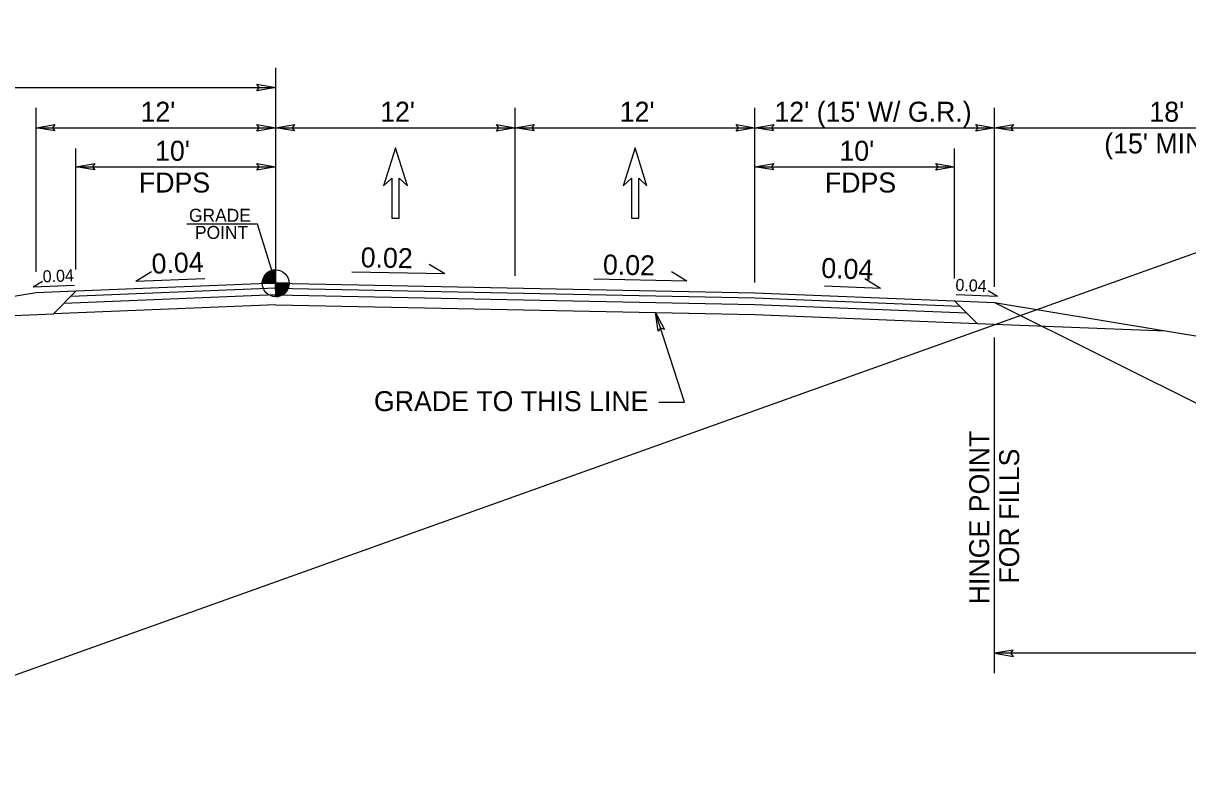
# Model space of a CAD drawing. Extents: x 1553195 to 1553792, y 810516 to 810787.
# Drawn here: x 1553561.6 to 1553619.9, y 810568.3 to 810606.6 of the extents above; entities that cross this region are included whole.
import ezdxf

# ---------------------------------------------------------------- set-up
doc = ezdxf.new("R2010")
doc.units = 0
for name, color, linetype in [('Old_Level_11', 7, 'Continuous'), ('Prop Dimension', 7, 'Continuous'), ('Prop DSN Text', 7, 'Continuous'), ('Prop Pavement Schedule Description CELL', 7, 'Continuous'), ('Prop Typical Section', 7, 'Continuous'), ('Sheet Sticker Incomplete CELL', 7, 'Continuous'), ('Typical Arrow Superelevation CELL', 7, 'Continuous'), ('Typical Pavement Slope CELL', 7, 'Continuous'), ('Typical Text ID Circle CELL', 7, 'Continuous'), ('z - Construction', 7, 'Continuous')]:
    doc.layers.add(name, color=color, linetype=linetype)

msp = doc.modelspace()

# ---------------------------------------------------------------- linework, layer by layer
at = {"layer": 'Old_Level_11'}
for p, q in [((1553574.205, 810593.587), (1553574.205, 810594.258)), ((1553573.534, 810593.587), (1553574.205, 810593.587)), ((1553574.206, 810592.916), (1553574.205, 810593.587)), ((1553574.876, 810593.587), (1553574.205, 810593.587)), ((1553574.205, 810593.587), (1553574.206, 810592.916))]:
    msp.add_line(p, q, dxfattribs=at)
for points in [[(1553573.554, 810593.751), (1553573.554, 810593.587)], [(1553573.568, 810593.797), (1553573.568, 810593.587)], [(1553573.581, 810593.835), (1553573.581, 810593.587)], [(1553573.595, 810593.866), (1553573.595, 810593.587)], [(1553573.608, 810593.894), (1553573.608, 810593.587)], [(1553573.622, 810593.918), (1553573.622, 810593.587)], [(1553573.635, 810593.941), (1553573.635, 810593.587)], [(1553573.648, 810593.961), (1553573.648, 810593.587)], [(1553573.662, 810593.981), (1553573.662, 810593.587)], [(1553573.675, 810593.999), (1553573.675, 810593.587)], [(1553573.689, 810594.015), (1553573.689, 810593.587)], [(1553573.702, 810594.032), (1553573.702, 810593.587)], [(1553573.716, 810594.046), (1553573.716, 810593.587)], [(1553573.729, 810594.06), (1553573.729, 810593.587)], [(1553573.742, 810594.073), (1553573.742, 810593.587)], [(1553573.756, 810594.085), (1553573.756, 810593.587)], [(1553573.769, 810594.097), (1553573.769, 810593.587)], [(1553573.783, 810594.109), (1553573.783, 810593.587)], [(1553573.796, 810594.12), (1553573.796, 810593.587)], [(1553573.809, 810594.129), (1553573.809, 810593.587)], [(1553573.823, 810594.139), (1553573.823, 810593.587)], [(1553573.836, 810594.148), (1553573.836, 810593.587)], [(1553573.85, 810594.157), (1553573.85, 810593.587)], [(1553573.863, 810594.164), (1553573.863, 810593.587)], [(1553573.877, 810594.172), (1553573.877, 810593.587)], [(1553573.89, 810594.179), (1553573.89, 810593.587)], [(1553573.903, 810594.187), (1553573.903, 810593.587)], [(1553573.917, 810594.193), (1553573.917, 810593.587)], [(1553573.93, 810594.199), (1553573.93, 810593.587)], [(1553573.944, 810594.205), (1553573.944, 810593.587)], [(1553573.957, 810594.211), (1553573.957, 810593.587)], [(1553573.971, 810594.217), (1553573.971, 810593.587)], [(1553573.984, 810594.221), (1553573.984, 810593.587)], [(1553573.998, 810594.225), (1553573.998, 810593.587)], [(1553574.011, 810594.23), (1553574.011, 810593.587)], [(1553574.024, 810594.233), (1553574.024, 810593.587)], [(1553574.038, 810594.237), (1553574.038, 810593.587)], [(1553574.051, 810594.24), (1553574.051, 810593.587)], [(1553574.065, 810594.243), (1553574.065, 810593.587)], [(1553574.078, 810594.246), (1553574.078, 810593.587)], [(1553574.091, 810594.249), (1553574.091, 810593.587)], [(1553574.105, 810594.251), (1553574.105, 810593.587)], [(1553574.118, 810594.252), (1553574.118, 810593.587)], [(1553574.132, 810594.254), (1553574.132, 810593.587)], [(1553574.145, 810594.255), (1553574.145, 810593.587)], [(1553574.159, 810594.257), (1553574.159, 810593.587)], [(1553574.172, 810594.257), (1553574.172, 810593.587)], [(1553574.185, 810594.258), (1553574.185, 810593.587)], [(1553574.199, 810594.258), (1553574.199, 810594.258), (1553574.199, 810593.587)], [(1553573.541, 810593.682), (1553573.541, 810593.587)], [(1553574.215, 810593.587), (1553574.215, 810592.916), (1553574.215, 810592.916)], [(1553574.229, 810593.587), (1553574.229, 810592.916)], [(1553574.242, 810593.587), (1553574.242, 810592.917)], [(1553574.256, 810593.587), (1553574.256, 810592.917)], [(1553574.269, 810593.587), (1553574.269, 810592.919)], [(1553574.282, 810593.587), (1553574.282, 810592.92)], [(1553574.296, 810593.587), (1553574.296, 810592.922)], [(1553574.309, 810593.587), (1553574.309, 810592.925)], [(1553574.323, 810593.587), (1553574.323, 810592.926)], [(1553574.336, 810593.587), (1553574.336, 810592.929)], [(1553574.35, 810593.587), (1553574.35, 810592.932)], [(1553574.363, 810593.587), (1553574.363, 810592.935)], [(1553574.376, 810593.587), (1553574.376, 810592.938)], [(1553574.39, 810593.587), (1553574.39, 810592.942)], [(1553574.403, 810593.587), (1553574.403, 810592.945)], [(1553574.417, 810593.587), (1553574.417, 810592.95)], [(1553574.43, 810593.587), (1553574.43, 810592.954)], [(1553574.444, 810593.587), (1553574.444, 810592.959)], [(1553574.457, 810593.587), (1553574.457, 810592.965)], [(1553574.47, 810593.587), (1553574.47, 810592.971)], [(1553574.484, 810593.587), (1553574.484, 810592.977)], [(1553574.497, 810593.587), (1553574.497, 810592.983)], [(1553574.511, 810593.587), (1553574.511, 810592.989)], [(1553574.524, 810593.587), (1553574.524, 810592.996)], [(1553574.538, 810593.587), (1553574.538, 810593.004)], [(1553574.551, 810593.587), (1553574.551, 810593.011)], [(1553574.564, 810593.587), (1553574.564, 810593.02)], [(1553574.578, 810593.587), (1553574.578, 810593.029)], [(1553574.591, 810593.587), (1553574.591, 810593.038)], [(1553574.605, 810593.587), (1553574.605, 810593.047)], [(1553574.618, 810593.587), (1553574.618, 810593.057)], [(1553574.632, 810593.587), (1553574.632, 810593.068)], [(1553574.645, 810593.587), (1553574.645, 810593.08)], [(1553574.658, 810593.587), (1553574.658, 810593.092)], [(1553574.672, 810593.587), (1553574.672, 810593.104)], [(1553574.685, 810593.587), (1553574.685, 810593.117)], [(1553574.699, 810593.587), (1553574.699, 810593.132)], [(1553574.712, 810593.587), (1553574.712, 810593.147)], [(1553574.726, 810593.587), (1553574.726, 810593.163)], [(1553574.739, 810593.587), (1553574.739, 810593.18)], [(1553574.752, 810593.587), (1553574.752, 810593.198)], [(1553574.766, 810593.587), (1553574.766, 810593.217)], [(1553574.779, 810593.587), (1553574.779, 810593.238)], [(1553574.793, 810593.587), (1553574.793, 810593.262)], [(1553574.806, 810593.587), (1553574.806, 810593.287)], [(1553574.82, 810593.587), (1553574.82, 810593.315)], [(1553574.833, 810593.587), (1553574.833, 810593.347)], [(1553574.846, 810593.587), (1553574.846, 810593.387)], [(1553574.86, 810593.587), (1553574.86, 810593.435)], [(1553574.873, 810593.587), (1553574.873, 810593.514)]]:
    msp.add_lwpolyline(points, dxfattribs=at)
msp.add_circle((1553574.206, 810593.587), 0.671, dxfattribs=at)
for start, end in [(90.00952, 180.00952), (270.00952, 0.00952)]:
    msp.add_arc((1553574.206, 810593.587), 0.671, start, end, dxfattribs=at)
at = {"layer": 'Prop Dimension'}
for p, q in [((1553582.672, 810594.051), (1553581.889, 810594.524)), ((1553567.205, 810593.683), (1553567.979, 810594.172)), ((1553567.205, 810593.683), (1553570.655, 810593.821)), ((1553582.672, 810594.051), (1553578.012, 810594.144)), ((1553594.803, 810593.69), (1553590.143, 810593.783)), ((1553594.803, 810593.69), (1553594.02, 810594.163)), ((1553604.487, 810593.325), (1553603.713, 810593.813)), ((1553562.066, 810593.402), (1553562.53, 810593.695)), ((1553562.066, 810593.402), (1553564.136, 810593.484)), ((1553604.487, 810593.325), (1553601.692, 810593.436)), ((1553610.345, 810592.922), (1553609.881, 810593.215)), ((1553610.345, 810592.922), (1553608.275, 810593.004))]:
    msp.add_line(p, q, dxfattribs=at)
at = {"layer": 'Prop DSN Text'}
for points in [[(1553573.268, 810603.547), (1553574.206, 810603.386), (1553573.263, 810603.219), (1553573.383, 810603.386)], [(1553563.143, 810601.212), (1553562.206, 810601.374), (1553563.148, 810601.54), (1553563.028, 810601.374)], [(1553573.268, 810601.535), (1553574.206, 810601.374), (1553573.263, 810601.207), (1553573.383, 810601.374)], [(1553575.143, 810601.212), (1553574.206, 810601.374), (1553575.148, 810601.54), (1553575.028, 810601.374)], [(1553585.268, 810601.535), (1553586.206, 810601.374), (1553585.263, 810601.207), (1553585.383, 810601.374)], [(1553587.143, 810601.212), (1553586.206, 810601.374), (1553587.148, 810601.54), (1553587.028, 810601.374)], [(1553597.268, 810601.535), (1553598.206, 810601.374), (1553597.263, 810601.207), (1553597.383, 810601.374)], [(1553599.143, 810601.212), (1553598.206, 810601.374), (1553599.148, 810601.54), (1553599.028, 810601.374)], [(1553609.268, 810601.535), (1553610.206, 810601.374), (1553609.263, 810601.207), (1553609.383, 810601.374)], [(1553611.143, 810601.212), (1553610.206, 810601.374), (1553611.148, 810601.54), (1553611.028, 810601.374)], [(1553565.143, 810599.257), (1553564.206, 810599.418), (1553565.148, 810599.585), (1553565.028, 810599.418)], [(1553573.268, 810599.579), (1553574.206, 810599.418), (1553573.263, 810599.251), (1553573.383, 810599.418)], [(1553599.143, 810599.257), (1553598.206, 810599.418), (1553599.148, 810599.585), (1553599.028, 810599.418)], [(1553607.268, 810599.579), (1553608.206, 810599.418), (1553607.263, 810599.251), (1553607.383, 810599.418)], [(1553593.365, 810591.181), (1553593.232, 810592.123), (1553593.679, 810591.277), (1553593.484, 810591.34)], [(1553611.143, 810575.223), (1553610.206, 810575.062), (1553611.148, 810574.895), (1553611.028, 810575.062)]]:
    msp.add_lwpolyline(points, close=True, dxfattribs=at)
at = {"layer": 'Prop Pavement Schedule Description CELL'}
for p, q in [((1553610.206, 810593.404), (1553610.206, 810602.374)), ((1553608.206, 810593.822), (1553608.206, 810600.332)), ((1553594.673, 810587.64), (1553593.232, 810592.123)), ((1553610.206, 810574.062), (1553610.206, 810590.871)), ((1553593.39, 810587.64), (1553594.673, 810587.64))]:
    msp.add_line(p, q, dxfattribs=at)
at = {"layer": 'Prop Typical Section'}
for points in [[(1553579.612, 810598.467), (1553580.018, 810598.842), (1553580.018, 810596.842), (1553580.393, 810596.842), (1553580.393, 810598.842), (1553580.799, 810598.467), (1553580.206, 810600.374)], [(1553591.612, 810598.467), (1553592.018, 810598.842), (1553592.018, 810596.842), (1553592.393, 810596.842), (1553592.393, 810598.842), (1553592.799, 810598.467), (1553592.206, 810600.374)]]:
    msp.add_lwpolyline(points, close=True, dxfattribs=at)
at = {"layer": 'Sheet Sticker Incomplete CELL'}
for p, q in [((1553564.206, 810593.187), (1553562.206, 810593.107)), ((1553562.206, 810593.107), (1553544.206, 810590.107)), ((1553608.206, 810592.707), (1553610.206, 810592.627)), ((1553610.206, 810592.627), (1553640.206, 810587.627)), ((1553610.206, 810592.627), (1553640.206, 810577.627)), ((1553553.653, 810591.682), (1553563.077, 810592.059)), ((1553609.334, 810591.579), (1553618.758, 810591.202))]:
    msp.add_line(p, q, dxfattribs=at)
at = {"layer": 'Typical Arrow Superelevation CELL'}
msp.add_line((1553652.472, 810606.601), (1553448.543, 810533.73), dxfattribs=at)
at = {"layer": 'Typical Pavement Slope CELL'}
for p, q in [((1553564.206, 810593.187), (1553563.077, 810592.059)), ((1553574.206, 810593.337), (1553563.945, 810592.927)), ((1553574.206, 810593.587), (1553564.206, 810593.187)), ((1553574.206, 810593.587), (1553598.206, 810593.107)), ((1553574.206, 810593.337), (1553598.206, 810592.857)), ((1553574.206, 810593.004), (1553563.598, 810592.579)), ((1553574.206, 810593.004), (1553598.206, 810592.524)), ((1553598.206, 810593.107), (1553608.206, 810592.707)), ((1553598.206, 810592.857), (1553608.466, 810592.447)), ((1553608.206, 810592.707), (1553609.334, 810591.579)), ((1553574.206, 810592.504), (1553563.077, 810592.059)), ((1553574.206, 810592.504), (1553598.206, 810592.024)), ((1553598.206, 810592.524), (1553608.813, 810592.099)), ((1553598.206, 810592.024), (1553609.334, 810591.579))]:
    msp.add_line(p, q, dxfattribs=at)
at = {"layer": 'Typical Text ID Circle CELL'}
msp.add_lwpolyline([(1553574.206, 810593.587), (1553573.302, 810596.541), (1553569.764, 810596.541)], dxfattribs=at)
at = {"layer": 'z - Construction'}
for p, q in [((1553574.206, 810594.276), (1553574.206, 810604.376)), ((1553544.206, 810603.386), (1553574.206, 810603.386)), ((1553562.206, 810594.159), (1553562.206, 810602.374)), ((1553586.206, 810593.951), (1553586.206, 810602.374)), ((1553598.206, 810593.627), (1553598.206, 810602.374)), ((1553562.206, 810601.374), (1553574.206, 810601.374)), ((1553574.206, 810601.374), (1553586.206, 810601.374)), ((1553586.206, 810601.374), (1553598.206, 810601.374)), ((1553598.206, 810601.374), (1553610.206, 810601.374)), ((1553610.206, 810601.374), (1553628.206, 810601.374)), ((1553564.206, 810594.276), (1553564.206, 810600.332)), ((1553564.206, 810599.418), (1553574.206, 810599.418)), ((1553598.206, 810599.418), (1553608.206, 810599.418)), ((1553640.206, 810575.062), (1553610.206, 810575.062))]:
    msp.add_line(p, q, dxfattribs=at)

# ---------------------------------------------------------------- texts
at = {"layer": 'Prop Pavement Schedule Description CELL'}
for s, p in [("12'", (1553567.437, 810601.674)), ("12'", (1553579.437, 810601.674)), ("12'", (1553591.437, 810601.674)), ("12' (15' W/ G.R.)", (1553599.183, 810601.674)), ("18'", (1553617.96, 810601.674)), ("10'", (1553568.167, 810599.718)), ("10'", (1553602.437, 810599.718)), ("(15' MIN.)", (1553615.698, 810600.086)), ('FDPS', (1553567.357, 810598.129)), ('FDPS', (1553601.71, 810598.129)), ('GRADE TO THIS LINE', (1553579.127, 810587.183))]:
    msp.add_text(s, height=1, dxfattribs=at).set_placement(p)
for s, height, rotation, p in [('0.04', 1, 2.29061, (1553568.012, 810594.058)), ('0.02', 1, 358.85413, (1553578.457, 810594.388)), ('0.02', 1, 358.85413, (1553590.588, 810594.027)), ('0.04', 1, 357.70939, (1553601.512, 810593.862)), ('0.04', 0.6, 2.29061, (1553562.551, 810593.627)), ('0.04', 0.6, 357.70939, (1553608.237, 810593.212)), ('HINGE POINT', 1, 90, (1553609.936, 810577.513)), ('FOR FILLS', 1, 90, (1553611.436, 810578.545))]:
    msp.add_text(s, height=height, rotation=rotation, dxfattribs=at).set_placement(p)
at = {"layer": 'Typical Text ID Circle CELL'}
for s, p in [('GRADE', (1553569.863, 810596.663)), ('POINT', (1553570.164, 810595.805))]:
    msp.add_text(s, height=0.6525, dxfattribs=at).set_placement(p)

doc.saveas('drawing.dxf')
